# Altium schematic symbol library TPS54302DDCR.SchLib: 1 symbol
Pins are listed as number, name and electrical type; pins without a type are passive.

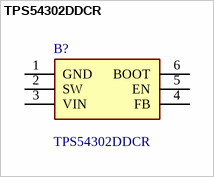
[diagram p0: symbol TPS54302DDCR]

## TPS54302DDCR
designator B?
Conv DC-DC 4.5V to 28V Synchronous Step Down Single-Out 0.6V to 26V 3A 6-Pin TSOT-23 T/R; Manufacturer_Name: Texas Instruments; Geometry.Height: 1.1mm
footprint SOT95P280X110-6N
pins: 1 GND, 2 SW, 3 VIN, 4 FB, 5 EN, 6 BOOT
